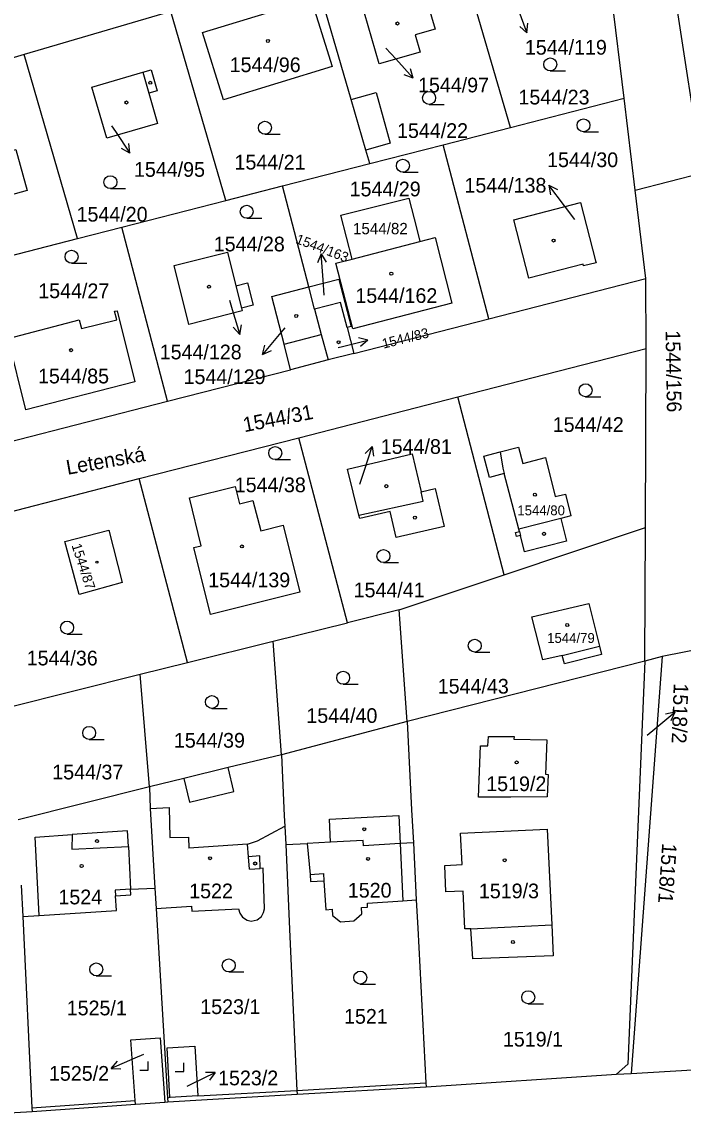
# Model space of a CAD drawing. Extents: x -724107 to -720612, y -1045267 to -1038441.
# Drawn here: x -722871.9 to -722795.4, y -1044248.7 to -1044121.9 of the extents above; entities that cross this region are included whole.
import ezdxf

# ---------------------------------------------------------------- set-up
doc = ezdxf.new("R2010")
doc.units = 0
for name, color, linetype in [('Hranice parcel', 7, 'Continuous'), ('Parcelní čísla', 7, 'Continuous'), ('Pop  PČ popisy', 7, 'Continuous'), ('Vnitřní kresba', 7, 'Continuous'), ('Značky budov', 7, 'Continuous'), ('Značky kultur', 7, 'Continuous')]:
    doc.layers.add(name, color=color, linetype=linetype)

msp = doc.modelspace()

# ---------------------------------------------------------------- linework, layer by layer
at = {"layer": 'Hranice parcel'}
for p, q in [((-722793.14, -1044139.35), (-722799.39, -1044098.74)), ((-722802.19, -1044130.71), (-722805.24, -1044106.23)), ((-722815.35, -1044134.1), (-722822.04, -1044111.15)), ((-722854.63, -1044120.69), (-722871.6, -1044125.66)), ((-722848.29, -1044142.55), (-722854.63, -1044120.69)), ((-722871.6, -1044125.66), (-722888.96, -1044130.74)), ((-722865.43, -1044146.94), (-722871.6, -1044125.66)), ((-722815.35, -1044134.1), (-722802.19, -1044130.71)), ((-722800.92, -1044141.35), (-722802.19, -1044130.71)), ((-722823.14, -1044136.1), (-722815.35, -1044134.1)), ((-722831.62, -1044138.27), (-722823.14, -1044136.1)), ((-722817.87, -1044156.2), (-722823.14, -1044136.1)), ((-722841.72, -1044140.86), (-722831.62, -1044138.27)), ((-722800.92, -1044141.35), (-722793.14, -1044139.35)), ((-722848.29, -1044142.55), (-722841.72, -1044140.86)), ((-722838.69, -1044152.52), (-722841.72, -1044140.86)), ((-722799.7, -1044151.54), (-722800.92, -1044141.35)), ((-722860.3, -1044145.63), (-722848.29, -1044142.55)), ((-722865.43, -1044146.94), (-722860.3, -1044145.63)), ((-722855.04, -1044165.75), (-722860.3, -1044145.63)), ((-722878.89, -1044150.39), (-722865.43, -1044146.94)), ((-722833.67, -1044149.31), (-722825.83, -1044147.27)), ((-722817.87, -1044156.2), (-722799.7, -1044151.54)), ((-722799.65, -1044159.64), (-722799.7, -1044151.54)), ((-722838.01, -1044155.1), (-722838.69, -1044152.52)), ((-722833.47, -1044160.21), (-722817.87, -1044156.2)), ((-722834.25, -1044157.23), (-722833.47, -1044160.21)), ((-722833.47, -1044160.21), (-722836.45, -1044160.97)), ((-722821.44, -1044165.24), (-722799.65, -1044159.64)), ((-722799.74, -1044180.34), (-722799.65, -1044159.64)), ((-722836.45, -1044160.97), (-722840.82, -1044162.12)), ((-722855.04, -1044165.75), (-722840.82, -1044162.12)), ((-722839.84, -1044169.97), (-722821.44, -1044165.24)), ((-722816.08, -1044185.81), (-722821.44, -1044165.24)), ((-722873.62, -1044170.52), (-722855.04, -1044165.75)), ((-722858.29, -1044174.66), (-722839.84, -1044169.97)), ((-722834.2, -1044191.35), (-722839.84, -1044169.97)), ((-722875.59, -1044179.16), (-722858.29, -1044174.66)), ((-722852.73, -1044195.95), (-722858.29, -1044174.66)), ((-722816.08, -1044185.81), (-722799.74, -1044180.34)), ((-722799.81, -1044195.8), (-722799.74, -1044180.34)), ((-722828.22, -1044189.87), (-722816.08, -1044185.81)), ((-722828.22, -1044189.87), (-722834.2, -1044191.35)), ((-722827.32, -1044202.77), (-722828.22, -1044189.87)), ((-722842.82, -1044193.49), (-722834.2, -1044191.35)), ((-722852.73, -1044195.95), (-722842.82, -1044193.49)), ((-722841.84, -1044206.6), (-722842.82, -1044193.49)), ((-722791.92, -1044194.08), (-722797.8, -1044195.25)), ((-722858.18, -1044197.3), (-722852.73, -1044195.95)), ((-722799.81, -1044195.8), (-722827.32, -1044202.77)), ((-722797.8, -1044195.25), (-722801.38, -1044243.45)), ((-722797.8, -1044195.25), (-722799.81, -1044195.8)), ((-722873.53, -1044201.14), (-722858.18, -1044197.3)), ((-722857.1, -1044210.3), (-722858.18, -1044197.3)), ((-722827.32, -1044202.77), (-722841.84, -1044206.6)), ((-722857.1, -1044210.3), (-722872.32, -1044214.15)), ((-722841.46, -1044214.88), (-722841.36, -1044216.99)), ((-722871.96, -1044221.68), (-722871.78, -1044225.3)), ((-722856.48, -1044222.02), (-722856.34, -1044224.38)), ((-722825.12, -1044245), (-722803.11, -1044243.55)), ((-722803.11, -1044243.55), (-722801.38, -1044243.45)), ((-722801.38, -1044243.45), (-722794.29, -1044243.02)), ((-722840.04, -1044245.86), (-722825.12, -1044245)), ((-722854.99, -1044246.74), (-722840.04, -1044245.86)), ((-722887.72, -1044248.72), (-722870.7, -1044247.86)), ((-722870.7, -1044247.86), (-722858.73, -1044247.01)), ((-722858.73, -1044247.01), (-722855.34, -1044246.77)), ((-722855.34, -1044246.77), (-722854.99, -1044246.74))]:
    msp.add_line(p, q, dxfattribs=at)
for points in [[(-722831.62, -1044138.27), (-722832.07, -1044136.73), (-722833.77, -1044130.87), (-722838.14, -1044115.86)], [(-722832.66, -1044119.43), (-722825.63, -1044117.39), (-722824.07, -1044122.74), (-722826.37, -1044123.4), (-722825.81, -1044125.38), (-722830.53, -1044126.75), (-722832.66, -1044119.43)], [(-722838.4, -1044119.25), (-722835.99, -1044127.05), (-722848.55, -1044130.92), (-722850.98, -1044123.13), (-722838.4, -1044119.25)], [(-722856.18, -1044133.62), (-722862.03, -1044135.32), (-722863.79, -1044129.43), (-722857.88, -1044127.72), (-722856.92, -1044127.44), (-722856.23, -1044129.87), (-722857.18, -1044130.15), (-722856.18, -1044133.62)], [(-722878.29, -1044138.19), (-722878.63, -1044136.92), (-722874.16, -1044135.69), (-722873.81, -1044136.97), (-722872.58, -1044136.63), (-722871.28, -1044141.39), (-722874.52, -1044142.27), (-722873.98, -1044144.28), (-722879.22, -1044145.71), (-722881.06, -1044138.95), (-722878.29, -1044138.19)], [(-722833.67, -1044149.31), (-722834.98, -1044144.24), (-722827.11, -1044142.27), (-722826.19, -1044145.85), (-722825.83, -1044147.27)], [(-722805.46, -1044149.73), (-722806.9, -1044150.1), (-722806.96, -1044149.89), (-722813.24, -1044151.5), (-722814.97, -1044144.76), (-722807.24, -1044142.78), (-722805.51, -1044149.52), (-722805.46, -1044149.73)], [(-722825.83, -1044147.27), (-722824.08, -1044146.81), (-722822.13, -1044154.4), (-722833.59, -1044157.36), (-722835.54, -1044149.8), (-722833.67, -1044149.31)], [(-722848.1, -1044148.52), (-722847.13, -1044152.4), (-722845.77, -1044152.06), (-722845.13, -1044154.63), (-722846.48, -1044154.97), (-722846.4, -1044155.31), (-722852.57, -1044156.86), (-722854.27, -1044150.07), (-722848.1, -1044148.52)], [(-722840.82, -1044162.12), (-722841.55, -1044159.15), (-722842.97, -1044153.65), (-722838.69, -1044152.52)], [(-722838.69, -1044152.52), (-722835.2, -1044151.62), (-722833.78, -1044157.1), (-722834.25, -1044157.23)], [(-722858.79, -1044163.5), (-722871.41, -1044166.74), (-722873.46, -1044158.48), (-722865.23, -1044156.35), (-722864.96, -1044157.34), (-722860.91, -1044156.32), (-722861.16, -1044155.35), (-722860.87, -1044155.29), (-722858.79, -1044163.5)], [(-722834.25, -1044157.23), (-722835.01, -1044154.32), (-722838.01, -1044155.1)], [(-722838.01, -1044155.1), (-722837.24, -1044158.02), (-722836.45, -1044160.97)], [(-722829.27, -1044178.49), (-722832.78, -1044179.31), (-722832.88, -1044178.92), (-722834.21, -1044173.58), (-722826.72, -1044171.84), (-722825.7, -1044176.22), (-722824.05, -1044175.83), (-722823.02, -1044180.21), (-722828.57, -1044181.51), (-722829.27, -1044178.49)], [(-722808.36, -1044178.99), (-722809.53, -1044179.29), (-722808.87, -1044181.91), (-722813.72, -1044183.14), (-722814.19, -1044181.26), (-722814.66, -1044181.38), (-722814.78, -1044180.91), (-722814.3, -1044180.79), (-722814.37, -1044180.53), (-722816.07, -1044174.09), (-722817.8, -1044174.54), (-722818.44, -1044172.1), (-722816.55, -1044171.61), (-722814.42, -1044171.07), (-722813.94, -1044172.94), (-722811.32, -1044172.26), (-722810.17, -1044176.77), (-722809, -1044176.47), (-722808.36, -1044178.99)], [(-722852, -1044182.64), (-722851.13, -1044182.45), (-722852.48, -1044176.91), (-722847.19, -1044175.6), (-722846.71, -1044177.59), (-722845.15, -1044177.22), (-722844.22, -1044180.72), (-722841.64, -1044180.07), (-722839.74, -1044187.81), (-722850.07, -1044190.39), (-722852, -1044182.64)], [(-722865.25, -1044188.1), (-722866.9, -1044181.95), (-722861.81, -1044180.63), (-722860.28, -1044186.7), (-722865.25, -1044188.1)], [(-722811.63, -1044195.65), (-722812.89, -1044190.67), (-722806.31, -1044189.11), (-722805.06, -1044194.04), (-722804.82, -1044195.01), (-722809.12, -1044196.1), (-722809.36, -1044195.15), (-722811.63, -1044195.65)], [(-722799.81, -1044195.8), (-722801.77, -1044242.39), (-722803.11, -1044243.55)], [(-722827.32, -1044202.77), (-722826.79, -1044212.97), (-722826.59, -1044216.8), (-722826.25, -1044223.39)], [(-722811.15, -1044204.89), (-722811.3, -1044208.87), (-722811, -1044208.88), (-722811.1, -1044211.48), (-722815.33, -1044211.53), (-722819.05, -1044211.53), (-722818.81, -1044205.57), (-722817.97, -1044205.56), (-722817.88, -1044204.51), (-722814.94, -1044204.48), (-722814.95, -1044204.79), (-722811.15, -1044204.89)], [(-722841.84, -1044206.6), (-722848.01, -1044208.1), (-722853.14, -1044209.34), (-722857.1, -1044210.3)], [(-722841.84, -1044206.6), (-722841.52, -1044213.68), (-722841.46, -1044214.88)], [(-722857.1, -1044210.3), (-722857.03, -1044212.84), (-722856.48, -1044222.02)], [(-722856.34, -1044224.38), (-722852.24, -1044224.13), (-722852.21, -1044224.69), (-722846.83, -1044224.41), (-722846.65, -1044224.92), (-722846.36, -1044225.38), (-722845.83, -1044225.72), (-722845.34, -1044225.83), (-722844.64, -1044225.7), (-722844.15, -1044225.31), (-722843.91, -1044224.86), (-722843.8, -1044224.42), (-722843.98, -1044219.73), (-722844.3, -1044219.75), (-722844.36, -1044218.28), (-722845.66, -1044218.41), (-722845.77, -1044216.94), (-722844.61, -1044216.54), (-722841.46, -1044214.88)], [(-722822.84, -1044222.46), (-722822.95, -1044219.4), (-722820.96, -1044219.31), (-722821.13, -1044215.69), (-722811.12, -1044215.22), (-722810.58, -1044226.28), (-722810.43, -1044229.86), (-722819.7, -1044230.21), (-722819.93, -1044226.72), (-722820.64, -1044226.72), (-722820.84, -1044222.37), (-722822.84, -1044222.46)], [(-722841.36, -1044216.99), (-722838.86, -1044216.86), (-722838.53, -1044220.44), (-722838.48, -1044221.27), (-722836.94, -1044221.17), (-722836.7, -1044224.52), (-722835.99, -1044224.47), (-722835.94, -1044225.19), (-722835, -1044225.91), (-722833.46, -1044225.79), (-722832.54, -1044224.98), (-722832.6, -1044224.27), (-722831.88, -1044224.22), (-722831.91, -1044223.78), (-722827.81, -1044223.5), (-722826.25, -1044223.39)], [(-722841.36, -1044216.99), (-722840.88, -1044227.65), (-722840.06, -1044245.41), (-722840.04, -1044245.86)], [(-722871.78, -1044225.3), (-722869.88, -1044225.18), (-722860.94, -1044224.63), (-722861.04, -1044222.91), (-722859.27, -1044222.82), (-722859.3, -1044222.16), (-722856.48, -1044222.02)], [(-722826.25, -1044223.39), (-722826.08, -1044226.66), (-722825.14, -1044244.55), (-722825.12, -1044245)], [(-722856.34, -1044224.38), (-722855.03, -1044246.29), (-722854.99, -1044246.74)], [(-722871.78, -1044225.3), (-722870.72, -1044247.41), (-722870.7, -1044247.86)], [(-722858.73, -1044247.01), (-722858.76, -1044246.56), (-722859.26, -1044239.56), (-722855.87, -1044239.32), (-722855.34, -1044246.77)], [(-722851.53, -1044246.05), (-722854.75, -1044246.24), (-722855.07, -1044240.49), (-722851.87, -1044240.3), (-722851.53, -1044246.05)]]:
    msp.add_lwpolyline(points, dxfattribs=at)
at = {"layer": 'Pop  PČ popisy'}
for p, q in [((-722814.52, -1044120.36), (-722813.45, -1044123.16)), ((-722813.45, -1044123.16), (-722814.27, -1044122.41)), ((-722813.45, -1044123.16), (-722813.34, -1044122.05)), ((-722829.76, -1044124.93), (-722828.63, -1044126.18)), ((-722828.63, -1044126.18), (-722826.62, -1044128.41)), ((-722826.62, -1044128.41), (-722826.92, -1044127.33)), ((-722826.62, -1044128.41), (-722827.66, -1044128)), ((-722861.5, -1044133.92), (-722861.05, -1044134.58)), ((-722861.05, -1044134.58), (-722859.37, -1044137.07)), ((-722859.37, -1044137.07), (-722859.52, -1044135.96)), ((-722859.37, -1044137.07), (-722860.35, -1044136.52)), ((-722809.12, -1044143.17), (-722810.93, -1044140.77)), ((-722810.93, -1044140.77), (-722809.92, -1044141.27)), ((-722810.93, -1044140.77), (-722810.72, -1044141.87)), ((-722807.91, -1044144.75), (-722809.12, -1044143.17)), ((-722837.25, -1044148.71), (-722837.68, -1044149.74)), ((-722837.04, -1044151.7), (-722837.25, -1044148.71)), ((-722837.25, -1044148.71), (-722836.68, -1044149.67)), ((-722836.92, -1044153.49), (-722837.04, -1044151.7)), ((-722847.86, -1044154.07), (-722847.54, -1044155.14)), ((-722847.54, -1044155.14), (-722846.66, -1044158.01)), ((-722846.66, -1044158.01), (-722847.43, -1044157.2)), ((-722846.66, -1044158.01), (-722846.48, -1044156.91)), ((-722841.46, -1044157.26), (-722842.1, -1044158.04)), ((-722842.1, -1044158.04), (-722844.03, -1044160.34)), ((-722834.77, -1044159.4), (-722831.86, -1044158.67)), ((-722831.86, -1044158.67), (-722832.95, -1044158.43)), ((-722831.86, -1044158.67), (-722832.71, -1044159.4)), ((-722844.03, -1044160.34), (-722843.77, -1044159.25)), ((-722844.03, -1044160.34), (-722843, -1044159.89)), ((-722835.27, -1044159.52), (-722834.77, -1044159.4)), ((-722832.29, -1044173.83), (-722831.36, -1044170.98)), ((-722831.36, -1044170.98), (-722832.15, -1044171.77)), ((-722831.36, -1044170.98), (-722831.2, -1044172.08)), ((-722832.77, -1044175.33), (-722832.29, -1044173.83)), ((-722798.64, -1044203.6), (-722796.34, -1044201.67)), ((-722796.34, -1044201.67), (-722797.43, -1044201.93)), ((-722796.34, -1044201.67), (-722796.79, -1044202.7)), ((-722799.53, -1044204.35), (-722798.64, -1044203.6)), ((-722857.81, -1044241.27), (-722858.79, -1044241.69)), ((-722858.79, -1044241.69), (-722861.55, -1044242.86)), ((-722861.55, -1044242.86), (-722860.83, -1044242.01)), ((-722861.55, -1044242.86), (-722860.44, -1044242.93)), ((-722852.2, -1044244.66), (-722849.5, -1044243.34)), ((-722849.5, -1044243.34), (-722850.62, -1044243.33)), ((-722849.5, -1044243.34), (-722850.18, -1044244.23)), ((-722852.76, -1044244.93), (-722852.2, -1044244.66))]:
    msp.add_line(p, q, dxfattribs=at)
at = {"layer": 'Vnitřní kresba'}
for p, q in [((-722857.88, -1044127.72), (-722857.18, -1044130.15)), ((-722833.77, -1044130.87), (-722830.89, -1044130.04)), ((-722830.89, -1044130.04), (-722829.26, -1044135.92)), ((-722829.26, -1044135.92), (-722832.07, -1044136.73)), ((-722847.13, -1044152.4), (-722846.48, -1044154.97)), ((-722841.55, -1044159.15), (-722837.24, -1044158.02)), ((-722816.55, -1044171.61), (-722816.23, -1044173.47)), ((-722816.23, -1044173.47), (-722816.07, -1044174.09)), ((-722825.45, -1044177.31), (-722825.7, -1044176.22)), ((-722832.88, -1044178.92), (-722825.45, -1044177.31)), ((-722809.53, -1044179.29), (-722814.37, -1044180.53)), ((-722814.3, -1044180.79), (-722814.19, -1044181.26)), ((-722809.36, -1044195.15), (-722805.06, -1044194.04)), ((-722847.34, -1044210.84), (-722848.01, -1044208.1)), ((-722853.14, -1044209.34), (-722852.47, -1044212.09)), ((-722852.47, -1044212.09), (-722847.34, -1044210.84)), ((-722857.03, -1044212.84), (-722854.84, -1044212.72)), ((-722854.84, -1044212.72), (-722854.76, -1044216.19)), ((-722836.3, -1044214.07), (-722828.28, -1044213.63)), ((-722828.28, -1044213.63), (-722828.1, -1044216.88)), ((-722836.16, -1044216.72), (-722836.3, -1044214.07)), ((-722870.32, -1044216.13), (-722866.07, -1044215.84)), ((-722869.88, -1044225.18), (-722870.32, -1044216.13)), ((-722866.07, -1044215.84), (-722866.08, -1044217.54)), ((-722859.64, -1044215.4), (-722866.07, -1044215.84)), ((-722859.55, -1044217.21), (-722859.64, -1044215.4)), ((-722854.76, -1044216.19), (-722852.59, -1044216.14)), ((-722852.59, -1044216.14), (-722852.56, -1044217.42)), ((-722866.08, -1044217.54), (-722859.55, -1044217.21)), ((-722859.55, -1044217.21), (-722859.3, -1044222.16)), ((-722845.77, -1044216.94), (-722852.56, -1044217.42)), ((-722836.16, -1044216.72), (-722838.86, -1044216.86)), ((-722832.39, -1044216.51), (-722836.16, -1044216.72)), ((-722832.35, -1044217.12), (-722832.39, -1044216.51)), ((-722828.1, -1044216.88), (-722832.35, -1044217.12)), ((-722826.59, -1044216.8), (-722828.1, -1044216.88)), ((-722828.1, -1044216.88), (-722827.81, -1044223.5)), ((-722845.56, -1044219.84), (-722845.66, -1044218.41)), ((-722845.56, -1044219.84), (-722844.3, -1044219.75)), ((-722838.53, -1044220.44), (-722837, -1044220.34)), ((-722837, -1044220.34), (-722836.94, -1044221.17)), ((-722859.3, -1044222.16), (-722861.07, -1044222.25)), ((-722861.07, -1044222.25), (-722861.04, -1044222.91)), ((-722819.93, -1044226.72), (-722810.58, -1044226.28)), ((-722851.53, -1044246.05), (-722840.06, -1044245.41)), ((-722840.06, -1044245.41), (-722825.14, -1044244.55)), ((-722870.72, -1044247.41), (-722858.76, -1044246.56)), ((-722854.75, -1044246.24), (-722855.03, -1044246.29))]:
    msp.add_line(p, q, dxfattribs=at)
at = {"layer": 'Značky budov'}
for centre, radius in [((-722828.43, -1044122.08), 0.175), ((-722843.42, -1044124.1), 0.175), ((-722857.03, -1044128.93), 0.175), ((-722859.78, -1044131.21), 0.175), ((-722810.37, -1044147.17), 0.175), ((-722829.14, -1044151), 0.175), ((-722850.23, -1044152.51), 0.175), ((-722840.14, -1044155.89), 0.175), ((-722835.24, -1044158.92), 0.175), ((-722866.18, -1044159.84), 0.175), ((-722829.72, -1044175.56), 0.175), ((-722812.53, -1044176.55), 0.175), ((-722826.41, -1044179.2), 0.175), ((-722811.48, -1044181.07), 0.175), ((-722846.43, -1044182.53), 0.175), ((-722863.19, -1044184.34), 0.117), ((-722808.79, -1044191.61), 0.175), ((-722814.64, -1044207.5), 0.175), ((-722832.27, -1044215.22), 0.175), ((-722863.18, -1044216.59), 0.175), ((-722850.1, -1044218.57), 0.175), ((-722831.82, -1044218.65), 0.175), ((-722816.02, -1044218.8), 0.175), ((-722864.96, -1044219.47), 0.175), ((-722844.89, -1044219.18), 0.175), ((-722815.08, -1044228.26), 0.175)]:
    msp.add_circle(centre, radius, dxfattribs=at)
at = {"layer": 'Značky kultur'}
for p, q in [((-722810.75, -1044127.56), (-722809, -1044127.56)), ((-722824.77, -1044131.43), (-722823.02, -1044131.43)), ((-722843.76, -1044134.88), (-722842.01, -1044134.88)), ((-722806.91, -1044134.6), (-722805.16, -1044134.6)), ((-722827.8, -1044139.27), (-722826.05, -1044139.27)), ((-722861.64, -1044141.17), (-722859.89, -1044141.17)), ((-722845.87, -1044144.59), (-722844.12, -1044144.59)), ((-722866.13, -1044149.79), (-722864.38, -1044149.79)), ((-722806.67, -1044165.23), (-722804.92, -1044165.23)), ((-722842.57, -1044172.49), (-722840.82, -1044172.49)), ((-722830.05, -1044184.39), (-722828.3, -1044184.39)), ((-722866.64, -1044192.66), (-722864.89, -1044192.66)), ((-722819.49, -1044194.75), (-722817.74, -1044194.75)), ((-722834.71, -1044198.46), (-722832.96, -1044198.46)), ((-722849.89, -1044201.26), (-722848.14, -1044201.26)), ((-722864.09, -1044204.83), (-722862.34, -1044204.83)), ((-722863.27, -1044232.17), (-722861.52, -1044232.17)), ((-722847.95, -1044231.71), (-722846.2, -1044231.71)), ((-722832.73, -1044233.12), (-722830.98, -1044233.12)), ((-722813.3, -1044235.39), (-722811.55, -1044235.39)), ((-722857.25, -1044243.07), (-722857.25, -1044242.07)), ((-722853.13, -1044243.23), (-722853.13, -1044242.23)), ((-722858.25, -1044243.07), (-722857.25, -1044243.07)), ((-722854.13, -1044243.23), (-722853.13, -1044243.23))]:
    msp.add_line(p, q, dxfattribs=at)
for centre in [(-722810.75, -1044126.81), (-722824.77, -1044130.68), (-722843.76, -1044134.13), (-722806.91, -1044133.85), (-722827.8, -1044138.52), (-722861.64, -1044140.42), (-722845.87, -1044143.84), (-722866.13, -1044149.04), (-722806.67, -1044164.48), (-722842.57, -1044171.74), (-722830.05, -1044183.64), (-722866.64, -1044191.91), (-722819.49, -1044194), (-722834.71, -1044197.71), (-722849.89, -1044200.51), (-722864.09, -1044204.08), (-722847.95, -1044230.96), (-722863.27, -1044231.42), (-722832.73, -1044232.37), (-722813.3, -1044234.64)]:
    msp.add_circle(centre, 0.75, dxfattribs=at)

# ---------------------------------------------------------------- texts
at = {"layer": 'Parcelní čísla'}
for s, height, p in [('1544/119', 1.7, (-722813.69, -1044125.68)), ('1544/96', 1.7, (-722847.84, -1044127.7)), ('1544/97', 1.7, (-722826.05, -1044130.04)), ('1544/23', 1.7, (-722814.43, -1044131.44)), ('1544/22', 1.7, (-722828.48, -1044135.31)), ('1544/21', 1.7, (-722847.28, -1044138.96)), ('1544/30', 1.7, (-722811.12, -1044138.68)), ('1544/95', 1.7, (-722858.91, -1044139.8)), ('1544/138', 1.7, (-722820.68, -1044141.63)), ('1544/29', 1.7, (-722833.96, -1044142.06)), ('1544/20', 1.7, (-722865.55, -1044144.98)), ('1544/82', 1.31, (-722833.57, -1044146.44)), ('1544/28', 1.7, (-722849.68, -1044148.42)), ('1544/27', 1.7, (-722869.98, -1044153.83)), ('1544/162', 1.7, (-722833.3, -1044154.38)), ('1544/128', 1.7, (-722855.93, -1044160.9)), ('1544/85', 1.7, (-722870.01, -1044163.68)), ('1544/129', 1.7, (-722853.17, -1044163.76)), ('1544/42', 1.7, (-722810.47, -1044169.29)), ('1544/81', 1.7, (-722830.36, -1044171.83)), ('1544/38', 1.7, (-722847.25, -1044176.26)), ('1544/80', 1.139, (-722814.56, -1044178.93)), ('1544/139', 1.7, (-722850.32, -1044187.25)), ('1544/41', 1.7, (-722833.5, -1044188.41)), ('1544/79', 1.139, (-722811.11, -1044193.68)), ('1544/36', 1.7, (-722871.32, -1044196.28)), ('1544/43', 1.7, (-722823.77, -1044199.54)), ('1544/40', 1.7, (-722838.97, -1044202.93)), ('1544/39', 1.7, (-722854.29, -1044205.79)), ('1544/37', 1.7, (-722868.36, -1044209.46)), ('1519/2', 1.7, (-722818.16, -1044210.81)), ('1524', 1.7, (-722867.65, -1044223.9)), ('1522', 1.7, (-722852.52, -1044223.2)), ('1520', 1.7, (-722834.17, -1044223.12)), ('1519/3', 1.7, (-722819.01, -1044223.2)), ('1525/1', 1.7, (-722866.69, -1044236.73)), ('1523/1', 1.7, (-722851.24, -1044236.58)), ('1521', 1.7, (-722834.61, -1044237.7)), ('1519/1', 1.7, (-722816.23, -1044240.34)), ('1525/2', 1.7, (-722868.74, -1044244.29)), ('1523/2', 1.7, (-722849.18, -1044244.82))]:
    msp.add_text(s, height=height, dxfattribs=at).set_placement(p)
for s, height, rotation, p in [('1544/163', 1.139, 339, (-722840.29, -1044147.44)), ('1544/83', 1.139, 14, (-722830.05, -1044159.67)), ('1544/156', 1.7, 271, (-722797.42, -1044157.56)), ('1544/31', 1.7, 11, (-722846.13, -1044169.33)), ('1544/87', 1.139, 288, (-722866.14, -1044182.4)), ('1518/2', 1.7, 268, (-722796.47, -1044198.33)), ('1518/1', 1.7, 266, (-722797.8, -1044216.8))]:
    msp.add_text(s, height=height, rotation=rotation, dxfattribs=at).set_placement(p)
at = {"layer": 'Pop  PČ popisy'}
msp.add_text('Letenská', height=1.7, rotation=10, dxfattribs=at).set_placement((-722866.59, -1044174.25))

doc.saveas('drawing.dxf')
